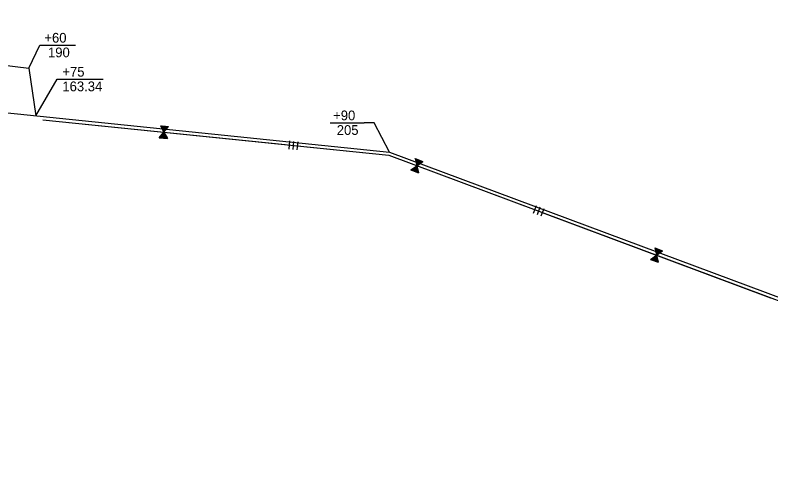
# Model space of a CAD drawing. Extents: x 979729 to 993523, y 1834148 to 1845433.
# Drawn here: x 981433.2 to 981898.4, y 1838420.8 to 1838700.8 of the extents above; entities that cross this region are included whole.
import ezdxf

# ---------------------------------------------------------------- set-up
doc = ezdxf.new("R2010")
doc.units = 0
for name, color, linetype in [('42', 7, 'Continuous'), ('51', 7, 'Continuous'), ('53', 7, 'Continuous'), ('R_Draft', 7, 'Continuous')]:
    doc.layers.add(name, color=color, linetype=linetype)

msp = doc.modelspace()

# ---------------------------------------------------------------- linework, layer by layer
at = {"layer": '42'}
for p, q in [((981450.18, 1838636.38), (981663.1, 1838614.53)), ((981522.68, 1838632.71), (981524.78, 1838628.73)), ((981522.73, 1838632.65), (981522.77, 1838632.7)), ((981522.87, 1838632.43), (981523.07, 1838632.67)), ((981522.98, 1838632.17), (981523.37, 1838632.64)), ((981523.12, 1838631.95), (981523.67, 1838632.61)), ((981523.24, 1838631.69), (981523.97, 1838632.58)), ((981523.35, 1838631.44), (981524.27, 1838632.55)), ((981523.49, 1838631.22), (981524.57, 1838632.52)), ((981523.67, 1838631.04), (981524.76, 1838632.36)), ((981523.76, 1838630.76), (981525.16, 1838632.46)), ((981523.9, 1838630.53), (981525.46, 1838632.43)), ((981524, 1838630.26), (981525.76, 1838632.39)), ((981524.15, 1838630.06), (981526.06, 1838632.36)), ((981524.25, 1838629.78), (981526.36, 1838632.33)), ((981524.39, 1838629.56), (981526.66, 1838632.3)), ((981524.5, 1838629.3), (981526.96, 1838632.27)), ((981524.66, 1838629.1), (981527.26, 1838632.24)), ((981524.76, 1838628.82), (981527.55, 1838632.21)), ((981524.78, 1838628.73), (981527.65, 1838632.2)), ((981521.91, 1838625.25), (981524.78, 1838628.73)), ((981523.37, 1838626.94), (981524.4, 1838625)), ((981523.55, 1838627.13), (981524.7, 1838624.96)), ((981523.7, 1838627.39), (981525, 1838624.93)), ((981523.9, 1838627.55), (981525.3, 1838624.9)), ((981524.05, 1838627.8), (981525.59, 1838624.87)), ((981524.23, 1838627.99), (981525.89, 1838624.84)), ((981524.39, 1838628.22), (981526.19, 1838624.81)), ((981524.59, 1838628.39), (981526.49, 1838624.78)), ((981524.74, 1838628.64), (981526.79, 1838624.75)), ((981524.78, 1838628.73), (981526.89, 1838624.74)), ((981521.98, 1838625.3), (981522.01, 1838625.24)), ((981522.16, 1838625.49), (981522.31, 1838625.21)), ((981522.32, 1838625.72), (981522.6, 1838625.18)), ((981522.5, 1838625.91), (981522.9, 1838625.15)), ((981522.67, 1838626.13), (981523.2, 1838625.12)), ((981522.83, 1838626.36), (981523.5, 1838625.09)), ((981523.01, 1838626.55), (981523.8, 1838625.06)), ((981523.22, 1838626.68), (981524.02, 1838625.17)), ((981602.13, 1838623.3), (981601.62, 1838618.33)), ((981604.62, 1838623.05), (981604.11, 1838618.07)), ((981607.11, 1838622.79), (981606.6, 1838617.82)), ((981663.1, 1838614.53), (982182.52, 1838420.85)), ((981679.36, 1838612.47), (981680.39, 1838608.08)), ((981679.4, 1838612.4), (981679.45, 1838612.44)), ((981679.48, 1838612.15), (981679.73, 1838612.33)), ((981679.52, 1838611.87), (981680.01, 1838612.23)), ((981679.6, 1838611.62), (981680.29, 1838612.12)), ((981679.64, 1838611.34), (981680.58, 1838612.02)), ((981679.69, 1838611.07), (981680.86, 1838611.91)), ((981679.77, 1838610.82), (981681.14, 1838611.81)), ((981679.9, 1838610.6), (981681.28, 1838611.61)), ((981679.92, 1838610.31), (981681.7, 1838611.6)), ((981680, 1838610.06), (981681.98, 1838611.49)), ((981680.02, 1838609.76), (981682.26, 1838611.39)), ((981680.12, 1838609.53), (981682.55, 1838611.28)), ((981680.14, 1838609.24), (981682.83, 1838611.18)), ((981680.22, 1838608.99), (981683.11, 1838611.07)), ((981680.27, 1838608.71), (981683.39, 1838610.97)), ((981680.37, 1838608.47), (981683.67, 1838610.86)), ((981680.39, 1838608.18), (981683.95, 1838610.76)), ((981680.39, 1838608.08), (981684.05, 1838610.72)), ((981676.74, 1838605.44), (981680.39, 1838608.08)), ((981676.81, 1838605.47), (981676.83, 1838605.41)), ((981677.04, 1838605.61), (981677.11, 1838605.3)), ((981677.25, 1838605.79), (981677.39, 1838605.2)), ((981677.48, 1838605.93), (981677.67, 1838605.09)), ((981677.69, 1838606.11), (981677.95, 1838604.99)), ((981677.91, 1838606.28), (981678.24, 1838604.88)), ((981678.13, 1838606.42), (981678.52, 1838604.78)), ((981678.37, 1838606.5), (981678.76, 1838604.84)), ((981678.58, 1838606.71), (981679.08, 1838604.57)), ((981678.8, 1838606.85), (981679.36, 1838604.46)), ((981679.01, 1838607.06), (981679.64, 1838604.36)), ((981679.24, 1838607.17), (981679.93, 1838604.25)), ((981679.45, 1838607.38), (981680.21, 1838604.15)), ((981679.67, 1838607.51), (981680.49, 1838604.04)), ((981679.89, 1838607.69), (981680.77, 1838603.94)), ((981680.12, 1838607.8), (981681.05, 1838603.83)), ((981680.33, 1838608.01), (981681.33, 1838603.73)), ((981680.39, 1838608.08), (981681.43, 1838603.7)), ((981753.88, 1838583.35), (981752.14, 1838578.66)), ((981756.23, 1838582.47), (981754.48, 1838577.79)), ((981758.57, 1838581.6), (981756.82, 1838576.92)), ((981826.94, 1838557.44), (981827.97, 1838553.05)), ((981826.97, 1838557.37), (981827.02, 1838557.41)), ((981827.05, 1838557.12), (981827.31, 1838557.3)), ((981827.09, 1838556.84), (981827.59, 1838557.2)), ((981827.17, 1838556.59), (981827.87, 1838557.09)), ((981824.32, 1838550.41), (981827.97, 1838553.05)), ((981827.22, 1838556.32), (981828.15, 1838556.99)), ((981827.25, 1838552.49), (981828.06, 1838549.02)), ((981827.27, 1838556.04), (981828.43, 1838556.88)), ((981827.34, 1838555.79), (981828.71, 1838556.78)), ((981827.46, 1838552.66), (981828.34, 1838548.91)), ((981827.47, 1838555.58), (981828.86, 1838556.58)), ((981827.49, 1838555.28), (981829.28, 1838556.57)), ((981827.57, 1838555.03), (981829.56, 1838556.46)), ((981827.59, 1838554.74), (981829.84, 1838556.36)), ((981827.69, 1838554.5), (981830.12, 1838556.25)), ((981827.69, 1838552.78), (981828.63, 1838548.81)), ((981827.72, 1838554.21), (981830.4, 1838556.15)), ((981827.79, 1838553.96), (981830.68, 1838556.04)), ((981827.84, 1838553.68), (981830.96, 1838555.94)), ((981827.9, 1838552.98), (981828.91, 1838548.7)), ((981827.94, 1838553.45), (981831.25, 1838555.83)), ((981827.97, 1838553.15), (981831.53, 1838555.73)), ((981827.97, 1838553.05), (981831.62, 1838555.69)), ((981827.97, 1838553.05), (981829, 1838548.67)), ((981824.39, 1838550.45), (981824.4, 1838550.38)), ((981824.61, 1838550.58), (981824.68, 1838550.28)), ((981824.83, 1838550.76), (981824.97, 1838550.17)), ((981825.05, 1838550.9), (981825.25, 1838550.07)), ((981825.27, 1838551.08), (981825.53, 1838549.96)), ((981825.48, 1838551.26), (981825.81, 1838549.86)), ((981825.71, 1838551.4), (981826.09, 1838549.75)), ((981825.94, 1838551.47), (981826.34, 1838549.81)), ((981826.15, 1838551.69), (981826.66, 1838549.54)), ((981826.38, 1838551.82), (981826.94, 1838549.44)), ((981826.58, 1838552.03), (981827.22, 1838549.33)), ((981826.81, 1838552.14), (981827.5, 1838549.23)), ((981827.02, 1838552.35), (981827.78, 1838549.12))]:
    msp.add_line(p, q, dxfattribs=at)
for points in [[(981450.18, 1838636.38), (981599.39, 1838621.07)], [(981522.68, 1838632.71), (981527.65, 1838632.2)], [(981521.91, 1838625.25), (981526.89, 1838624.74)], [(981606.85, 1838620.3), (981663.1, 1838614.53), (981750.67, 1838581.88)], [(981679.36, 1838612.47), (981684.05, 1838610.72)], [(981676.74, 1838605.44), (981681.43, 1838603.7)], [(981757.69, 1838579.26), (981898.24, 1838526.85)], [(981826.94, 1838557.44), (981831.62, 1838555.69)], [(981824.32, 1838550.41), (981829, 1838548.67)]]:
    msp.add_lwpolyline(points, dxfattribs=at)
at = {"layer": '51'}
msp.add_lwpolyline([(981283.24, 1838700.78), (981406.41, 1838642.88), (981663.56, 1838616.49), (982183.3, 1838422.69)], dxfattribs=at)
at = {"layer": '53'}
msp.add_lwpolyline([(981406.41, 1838642.88), (981416.24, 1838671.23), (981441.63, 1838668.06), (981445.84, 1838638.84)], dxfattribs=at)
at = {"layer": 'R_Draft'}
for p, q in [((981454.44, 1838682.33), (981470.23, 1838682.33)), ((981465.08, 1838661.41), (981487.43, 1838661.41)), ((981627.07, 1838634.54), (981648.09, 1838634.54))]:
    msp.add_line(p, q, dxfattribs=at)
for points in [[(981441.63, 1838668.06), (981448.44, 1838682.33), (981454.44, 1838682.33)], [(981445.84, 1838638.84), (981459.08, 1838661.41), (981465.08, 1838661.41)], [(981663.56, 1838616.49), (981654.09, 1838634.54), (981648.09, 1838634.54)]]:
    msp.add_lwpolyline(points, dxfattribs=at)

# ---------------------------------------------------------------- texts
for s, p in [('+60', (981451.18, 1838683.83)), (' 190', (981451.18, 1838674.83)), ('+75', (981462.26, 1838662.91)), ('163.34', (981462.26, 1838653.91)), ('+90', (981628.94, 1838636.04)), (' 205', (981628.94, 1838627.04))]:
    msp.add_text(s, height=6, rotation=360, dxfattribs=at).set_placement(p)

doc.saveas('drawing.dxf')
